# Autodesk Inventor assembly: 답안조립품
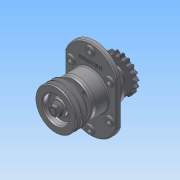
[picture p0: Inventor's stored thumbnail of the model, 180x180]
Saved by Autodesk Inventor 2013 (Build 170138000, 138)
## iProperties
Created: 2015-02
Part Number: 답안조립품
Document SubType Name: Assembly
Designer: ST5
Author: ST5
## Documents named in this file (11)
- C:\Users\ST5\Desktop\450207V1012\답안조립품.iam
- C:\Users\ST5\Desktop\450207V1012\1 본체.ipt
- C:\Users\ST5\Desktop\450207V1012\3-축.ipt
- C:\Users\ST5\Desktop\450207V1012\11-키 6x6.ipt
- C:\Users\ST5\Desktop\450207V1012\2-커버.ipt
- C:\Users\ST5\Desktop\450207V1012\10-M6.ipt
- C:\Users\ST5\Desktop\450207V1012\8-오일실 30x42.ipt
- C:\Users\ST5\Desktop\450207V1012\6-베어링 6206.ipt
- C:\Users\ST5\Desktop\450207V1012\4-V벨트풀리.ipt
- C:\Users\ST5\Desktop\450207V1012\9-M16-너트.ipt
- C:\Users\ST5\Desktop\450207V1012\5-체인 스프로킷.ipt
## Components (22 placed, 10 different names)
1. 1 본체:1 — 각도:3, 각도:4
2. 3-축:1 — 각도:1, 각도:2
3. 11-키 6x6:1 — 각도:1
4. 11-키 6x6:2 — 각도:2
5. 2-커버:1 — 플러쉬:1
6. 2-커버:2 — 플러쉬:2
7. 8-8-오일실 30x42:1 — 플러쉬:1
8. 8-8-오일실 30x42:2 — 플러쉬:2
9. 6-베어링 6206:1
10. 6-베어링 6206:2
11. 4-V벨트풀리:1
12. 9-M16 너트:1 — 각도:3
13. 5-체인 스프로킷:1
14. 9-M16 너트:2 — 각도:4
15. 10-M6:1
16. 10-M6:2
17. 10-M6:3
18. 10-M6:4
19. 10-M6:5
20. 10-M6:6
21. 10-M6:7
22. 10-M6:8
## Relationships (6: Angle 4, Flush 2)
- 각도:1 [Angle]: 3-축:1 ↔ 11-키 6x6:1
- 각도:2 [Angle]: 3-축:1 ↔ 11-키 6x6:2
- 플러쉬:1 [Flush]: 2-커버:1 ↔ 8-8-오일실 30x42:1
- 플러쉬:2 [Flush]: 2-커버:2 ↔ 8-8-오일실 30x42:2
- 각도:3 [Angle]: 1 본체:1 ↔ 9-M16 너트:1
- 각도:4 [Angle]: 1 본체:1 ↔ 9-M16 너트:2
